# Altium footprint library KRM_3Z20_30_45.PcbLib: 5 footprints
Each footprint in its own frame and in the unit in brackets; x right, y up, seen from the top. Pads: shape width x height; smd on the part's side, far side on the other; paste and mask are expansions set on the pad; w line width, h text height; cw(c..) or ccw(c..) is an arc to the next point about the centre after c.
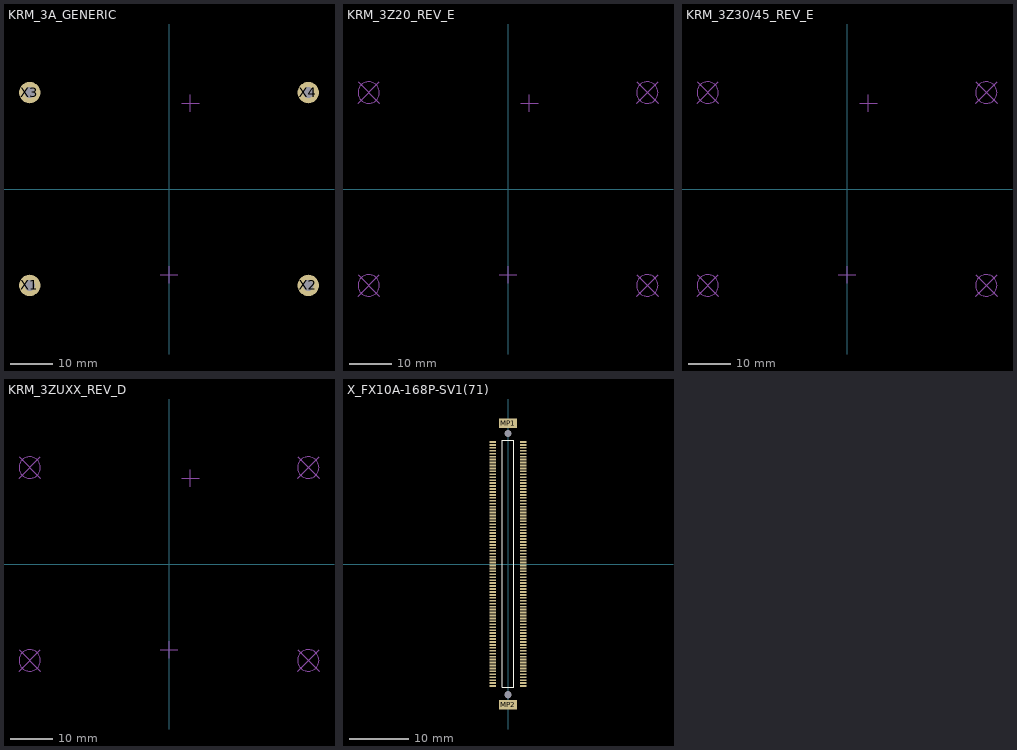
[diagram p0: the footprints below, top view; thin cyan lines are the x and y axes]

## KRM_3A_GENERIC [mm] "KR3000 series Module"
pads (4):
  round 5 / inner round 5 / far side round 5.5 hole 2.5: X1(-32.5,-22.5) X2(32.5,-22.5) X3(-32.5,22.5) X4(32.5,22.5)
Mechanical 1:
  lines w0.25: -2,-20 0,-20 ; 0,-22 0,-20 ; 0,-18 0,-20 ; 2,-20 0,-20 ; 3,20 5,20 ; 5,18 5,20 ; 5,22 5,20 ; 7,20 5,20
  text "168" at -20.5,-22.5 h2
  text "167" at -20.5,-19 h2
  text "2" at 21.5,-22.5 h2
  text "1" at 21.5,-19 h2
  text "X1_MGT" at -13.5,-20.5 h2
  text "1" at 26.5,21 h2
  text "2" at 26.5,17.5 h2
  text "167" at -15.5,21 h2
  text "168" at -15.5,17.5 h2
  text "X2_1" at 20,19.5 h2
  text "X2_2" at 10,19.5 h2
  text "X1_2" at 4,-20.5 h2
  text "X1_1" at 14,-20.5 h2
  text "X2_MIO" at -8.5,19.5 h2

## KRM_3Z20_REV_E [mm] "KR3000 series Module ZYNQ7020 VERSION_E"
Mechanical 1:
  circle w0.1: c-32.5,22.5 r2.5
  circle w0.1: c-32.5,-22.5 r2.5
  circle w0.1: c32.5,-22.5 r2.5
  circle w0.1: c32.5,22.5 r2.5
  lines w0.1: -35,-25 -30,-20 ; -35,-20 -30,-25 ; -35,20 -30,25 ; -35,25 -30,20 ; 30,-25 35,-20 ; 30,-20 35,-25 ; 30,20 35,25 ; 30,25 35,20
  lines w0.25: -2,-20 0,-20 ; 0,-22 0,-20 ; 0,-18 0,-20 ; 2,-20 0,-20 ; 3,20 5,20 ; 5,18 5,20 ; 5,22 5,20 ; 7,20 5,20
3D body "KRM-3Z7020_REV_E.step": height 8.84, standoff 1.74, extent -35,-25 35,25

## KRM_3Z30/45_REV_E [mm] "KR3000 series Module ZYNQ7030/45 VERSION_E"
Mechanical 1:
  circle w0.1: c32.5,22.5 r2.5
  circle w0.1: c32.5,-22.5 r2.5
  circle w0.1: c-32.5,22.5 r2.5
  circle w0.1: c-32.5,-22.5 r2.5
  lines w0.1: -35,-25 -30,-20 ; -35,-20 -30,-25 ; -35,20 -30,25 ; -35,25 -30,20 ; 30,-25 35,-20 ; 30,-20 35,-25 ; 30,20 35,25 ; 30,25 35,20
  lines w0.25: -2,-20 0,-20 ; 0,-22 0,-20 ; 0,-18 0,-20 ; 2,-20 0,-20 ; 3,20 5,20 ; 5,18 5,20 ; 5,22 5,20 ; 7,20 5,20
3D body "KRM-3Z7030_35_45_REV_F.step": height 9.77, standoff 1.71, extent -35,-25 35,25

## KRM_3ZUXX_REV_D [mm] "KR3000 series Module ZYNQ ZUxx VERSION_D"
Mechanical 1:
  circle w0.1: c32.5,22.5 r2.5
  circle w0.1: c32.5,-22.5 r2.5
  circle w0.1: c-32.5,22.5 r2.5
  circle w0.1: c-32.5,-22.5 r2.5
  lines w0.1: -35,-25 -30,-20 ; -35,-20 -30,-25 ; -35,20 -30,25 ; -35,25 -30,20 ; 30,-25 35,-20 ; 30,-20 35,-25 ; 30,20 35,25 ; 30,25 35,20
  lines w0.25: -2,-20 0,-20 ; 0,-22 0,-20 ; 0,-18 0,-20 ; 2,-20 0,-20 ; 3,20 5,20 ; 5,18 5,20 ; 5,22 5,20 ; 7,20 5,20
3D body "KRM-3ZUXX_REV_D.step": height 9.92, standoff 1.64, extent -35,-25 35,25

## X_FX10A-168P-SV1(71) [mm]
pads (172):
  rrect12% 1.1x0.3 smd paste-0.025: 1(-2.6,20.75) 2(2.6,20.75) 3(-2.6,20.25) 4(2.6,20.25) 5(-2.6,19.75) 6(2.6,19.75) 7(-2.6,19.25) 8(2.6,19.25) 9(-2.6,18.75) 10(2.6,18.75) 11(-2.6,18.25) 12(2.6,18.25) 13(-2.6,17.75) 14(2.6,17.75) 15(-2.6,17.25) 16(2.6,17.25) 17(-2.6,16.75) 18(2.6,16.75) 19(-2.6,16.25) 20(2.6,16.25) 21(-2.6,15.75) 22(2.6,15.75) 23(-2.6,15.25) 24(2.6,15.25) 25(-2.6,14.75) 26(2.6,14.75) 27(-2.6,14.25) 28(2.6,14.25) 29(-2.6,13.75) 30(2.6,13.75) 31(-2.6,13.25) 32(2.6,13.25) 33(-2.6,12.75) 34(2.6,12.75) 35(-2.6,12.25) 36(2.6,12.25) 37(-2.6,11.75) 38(2.6,11.75) 39(-2.6,11.25) 40(2.6,11.25) 41(-2.6,10.75) 42(2.6,10.75) 43(-2.6,10.25) 44(2.6,10.25) 45(-2.6,9.75) 46(2.6,9.75) 47(-2.6,9.25) 48(2.6,9.25) 49(-2.6,8.75) 50(2.6,8.75) 51(-2.6,8.25) 52(2.6,8.25) 53(-2.6,7.75) 54(2.6,7.75) 55(-2.6,7.25) 56(2.6,7.25) 57(-2.6,6.75) 58(2.6,6.75) 59(-2.6,6.25) 60(2.6,6.25) 61(-2.6,5.75) 62(2.6,5.75) 63(-2.6,5.25) 64(2.6,5.25) 65(-2.6,4.75) 66(2.6,4.75) 67(-2.6,4.25) 68(2.6,4.25) 69(-2.6,3.75) 70(2.6,3.75) 71(-2.6,3.25) 72(2.6,3.25) 73(-2.6,2.75) 74(2.6,2.75) 75(-2.6,2.25) 76(2.6,2.25) 77(-2.6,1.75) 78(2.6,1.75) 79(-2.6,1.25) 80(2.6,1.25) 81(-2.6,0.75) 82(2.6,0.75) 83(-2.6,0.25) 84(2.6,0.25) 85(-2.6,-0.25) 86(2.6,-0.25) 87(-2.6,-0.75) 88(2.6,-0.75) 89(-2.6,-1.25) 90(2.6,-1.25) 91(-2.6,-1.75) 92(2.6,-1.75) 93(-2.6,-2.25) 94(2.6,-2.25) 95(-2.6,-2.75) 96(2.6,-2.75) 97(-2.6,-3.25) 98(2.6,-3.25) 99(-2.6,-3.75) 100(2.6,-3.75) 101(-2.6,-4.25) 102(2.6,-4.25) 103(-2.6,-4.75) 104(2.6,-4.75)
  rrect25% 1.1x0.3 smd: 105(-2.6,-5.25) 106(2.6,-5.25) 107(-2.6,-5.75) 108(2.6,-5.75) 109(-2.6,-6.25) 110(2.6,-6.25) 111(-2.6,-6.75) 112(2.6,-6.75) 113(-2.6,-7.25) 114(2.6,-7.25) 115(-2.6,-7.75) 116(2.6,-7.75) 117(-2.6,-8.25) 118(2.6,-8.25) 119(-2.6,-8.75) 120(2.6,-8.75) 121(-2.6,-9.25) 122(2.6,-9.25) 123(-2.6,-9.75) 124(2.6,-9.75) 125(-2.6,-10.25) 126(2.6,-10.25) 127(-2.6,-10.75) 128(2.6,-10.75) 129(-2.6,-11.25) 130(2.6,-11.25) 131(-2.6,-11.75) 132(2.6,-11.75) 133(-2.6,-12.25) 134(2.6,-12.25) 135(-2.6,-12.75) 136(2.6,-12.75) 137(-2.6,-13.25) 138(2.6,-13.25) 139(-2.6,-13.75) 140(2.6,-13.75) 141(-2.6,-14.25) 142(2.6,-14.25) 143(-2.6,-14.75) 144(2.6,-14.75) 145(-2.6,-15.25) 146(2.6,-15.25) 147(-2.6,-15.75) 148(2.6,-15.75) 149(-2.6,-16.25) 150(2.6,-16.25) 151(-2.6,-16.75) 152(2.6,-16.75) 153(-2.6,-17.25) 154(2.6,-17.25) 155(-2.6,-17.75) 156(2.6,-17.75) 157(-2.6,-18.25) 158(2.6,-18.25) 159(-2.6,-18.75) 160(2.6,-18.75) 161(-2.6,-19.25) 162(2.6,-19.25) 163(-2.6,-19.75) 164(2.6,-19.75) 165(-2.6,-20.25) 166(2.6,-20.25) 167(-2.6,-20.75) 168(2.6,-20.75)
  rrect12% 3.1x1.6 smd: MP1(0,23.95) MP2(0,-23.95)
  round 1.1 hole 1.15 unplated: X1(0,22.2)
  round 1.1 hole 1.25 unplated: X2(0,-22.2)
Top Overlay:
  lines w0.1: -1,-20.95 1,-20.95 1,21.05 -1,21.05 -1,-20.95
Top Solder:
  text "1" at -2.75,23.2 h1.2
3D body "FX10A-168P-SV1.stp": height 4.51, standoff -0.59, extent -2.941,-24.55 2.959,24.55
